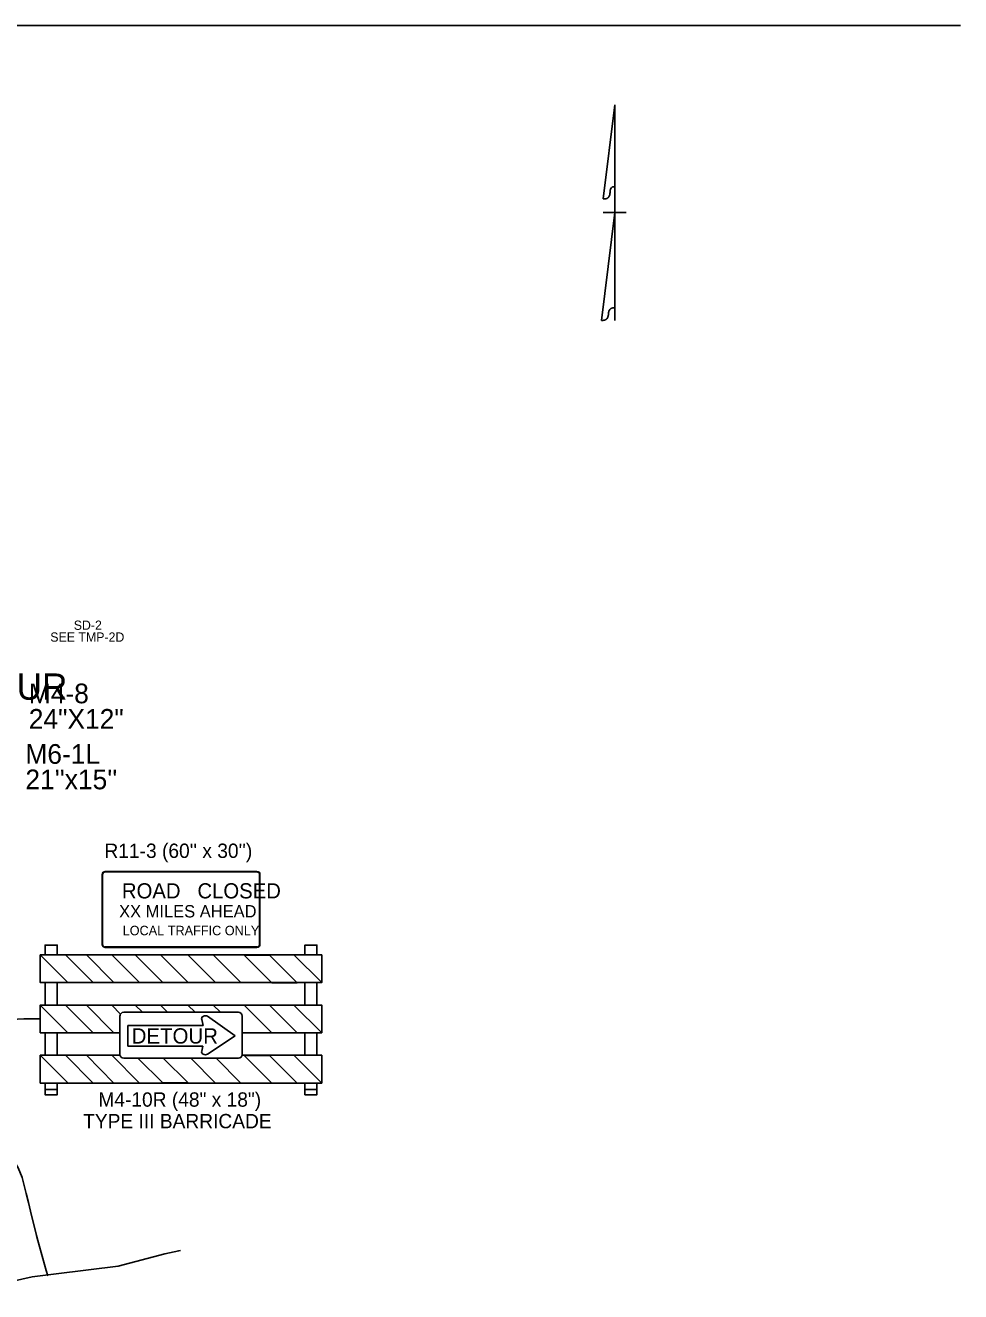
# Model space of a CAD drawing. Extents: x 886234 to 968767, y 455416 to 684046.
# Drawn here: x 928577 to 936553, y 478392 to 489183 of the extents above; entities that cross this region are included whole.
import ezdxf

# ---------------------------------------------------------------- set-up
doc = ezdxf.new("R2010")
doc.units = 0
for name, color, linetype in [('Scratch_Level_3', 7, 'Continuous'), ('TC DEV BARRICADE', 7, 'Continuous'), ('TC DEV SIGN BLACK 239', 7, 'Continuous'), ('TC DEV SIGN BLACK ZERO', 7, 'Continuous'), ('TC DEV SIGN ORANGE', 7, 'Continuous'), ('TC DEV SIGN WHITE', 7, 'Continuous'), ('TC LABEL TEXT', 7, 'Continuous'), ('TC SHEET LAYOUT SHAPE', 7, 'Continuous')]:
    doc.layers.add(name, color=color, linetype=linetype)

msp = doc.modelspace()

# ---------------------------------------------------------------- linework, layer by layer
at = {"layer": 'Scratch_Level_3'}
msp.add_line((904674, 489183), (936553, 489183), dxfattribs=at)
at = {"layer": 'TC DEV BARRICADE'}
for p, q in [((928921, 481261), (928705, 481261)), ((928705, 481261), (928940, 481026)), ((929157, 481026), (928921, 481261)), ((929314, 481261), (929098, 481261)), ((929098, 481261), (929333, 481026)), ((929550, 481026), (929314, 481261)), ((929730, 481261), (929514, 481261)), ((929514, 481261), (929749, 481026)), ((929965, 481026), (929730, 481261)), ((930180, 481261), (929964, 481261)), ((929964, 481261), (930200, 481026)), ((930416, 481026), (930180, 481261)), ((930660, 481260), (930444, 481260)), ((930444, 481260), (930679, 481025)), ((930895, 481025), (930660, 481260)), ((931105, 481261), (930867, 481261)), ((930867, 481261), (931105, 481026)), ((931105, 481026), (931105, 481261)), ((928940, 481026), (929157, 481026)), ((929333, 481026), (929550, 481026)), ((929749, 481026), (929965, 481026)), ((930200, 481026), (930416, 481026)), ((930679, 481025), (930895, 481025)), ((928921, 480834), (928705, 480834)), ((928705, 480834), (928940, 480598)), ((929157, 480598), (928921, 480834)), ((929314, 480833), (929098, 480833)), ((929098, 480833), (929333, 480598)), ((929314, 480833), (929098, 480833)), ((929098, 480833), (929333, 480598)), ((929390, 480758), (929314, 480833)), ((929390, 480758), (929314, 480833)), ((929730, 480834), (929514, 480834)), ((929514, 480834), (929575, 480773)), ((929514, 480834), (929575, 480773)), ((929791, 480773), (929730, 480834)), ((929791, 480773), (929730, 480834)), ((930180, 480833), (929964, 480833)), ((929964, 480833), (930025, 480773)), ((930180, 480833), (929964, 480833)), ((929964, 480833), (930025, 480773)), ((930241, 480773), (930180, 480833)), ((930241, 480773), (930180, 480833)), ((930660, 480832), (930444, 480832)), ((930444, 480832), (930679, 480597)), ((930895, 480597), (930660, 480832)), ((931105, 480834), (930867, 480834)), ((930867, 480834), (931105, 480598)), ((931105, 480598), (931105, 480834)), ((929384, 480598), (929384, 480740)), ((929575, 480773), (929791, 480773)), ((930025, 480773), (930241, 480773)), ((928940, 480598), (929157, 480598)), ((929333, 480598), (929384, 480598)), ((929333, 480598), (929384, 480598)), ((930679, 480597), (930895, 480597)), ((928921, 480406), (928705, 480406)), ((928705, 480406), (928940, 480171)), ((929157, 480170), (928921, 480406)), ((929314, 480406), (929098, 480406)), ((929098, 480406), (929333, 480170)), ((929550, 480170), (929314, 480406)), ((929538, 480382), (929749, 480171)), ((929538, 480382), (929749, 480171)), ((929754, 480382), (929538, 480382)), ((929965, 480171), (929754, 480382)), ((929965, 480171), (929754, 480382)), ((929988, 480382), (930200, 480170)), ((930204, 480382), (929988, 480382)), ((929988, 480382), (930199, 480170)), ((930416, 480170), (930204, 480382)), ((930415, 480170), (930204, 480382)), ((930660, 480404), (930444, 480404)), ((930444, 480404), (930679, 480169)), ((930895, 480169), (930660, 480404)), ((931105, 480406), (930867, 480406)), ((930867, 480406), (931105, 480170)), ((931105, 480170), (931105, 480406)), ((928940, 480171), (929157, 480170)), ((929333, 480170), (929550, 480170)), ((929749, 480171), (929965, 480171)), ((929749, 480171), (929965, 480171)), ((930200, 480170), (930416, 480170)), ((930679, 480169), (930895, 480169)), ((928746, 480116), (928849, 480116)), ((931064, 480116), (930962, 480116))]:
    msp.add_line(p, q, dxfattribs=at)
for points in [[(928746, 481263), (928746, 481346), (928849, 481346), (928849, 481263)], [(931064, 481263), (931064, 481346), (930962, 481346), (930962, 481263)], [(929317, 481261), (928705, 481261), (928705, 481026), (931105, 481026), (931105, 481261), (930542, 481261)], [(930542, 481261), (929317, 481261)], [(928746, 480836), (928746, 481027)], [(928849, 481028), (928849, 480838)], [(930962, 481028), (930962, 480838)], [(931064, 480836), (931064, 481027)], [(929317, 480834), (928705, 480834), (928705, 480598), (929384, 480598)], [(930542, 480834), (929317, 480834)], [(929730, 480834), (929730, 480834), (929514, 480834)], [(930426, 480598), (931105, 480598), (931105, 480834), (930542, 480834)], [(928746, 480406), (928746, 480598)], [(928849, 480597), (928849, 480408)], [(930962, 480597), (930962, 480408)], [(931064, 480406), (931064, 480598)], [(929317, 480406), (928705, 480406), (928705, 480170), (931105, 480170), (931105, 480406), (930542, 480406)], [(929384, 480406), (929317, 480406)], [(930542, 480406), (930426, 480406)], [(928849, 480169), (928849, 480070), (928746, 480070), (928746, 480170)], [(930199, 480170), (930200, 480170), (930415, 480170)], [(930962, 480169), (930962, 480070), (931064, 480070), (931064, 480170)]]:
    msp.add_lwpolyline(points, dxfattribs=at)
msp.add_arc((929417, 480740), 32.6, 146.236, 180, dxfattribs=at)
at = {"layer": 'TC DEV SIGN BLACK 239'}
msp.add_line((930552, 481326), (929259, 481326), dxfattribs=at)
for points in [[(929259, 481972), (930552, 481972)], [(929233, 481351), (929233, 481947)], [(930578, 481947), (930578, 481351)]]:
    msp.add_lwpolyline(points, dxfattribs=at)
for centre, start, end in [((929259, 481947), 90, 180), ((930552, 481947), 0, 90), ((929259, 481351), 180, 270.0009), ((930552, 481351), 270.0009, 360)]:
    msp.add_arc(centre, 25.9, start, end, dxfattribs=at)
at = {"layer": 'TC DEV SIGN BLACK ZERO'}
for p, q in [((929384, 480740), (929384, 480414)), ((930394, 480773), (929417, 480773)), ((930093, 480660), (930081, 480712)), ((930131, 480739), (930368, 480572)), ((930426, 480414), (930426, 480740)), ((929450, 480485), (929450, 480660)), ((929450, 480660), (930093, 480660)), ((930368, 480572), (930131, 480415)), ((930091, 480485), (929450, 480485)), ((930081, 480442), (930091, 480485)), ((929417, 480382), (930394, 480382))]:
    msp.add_line(p, q, dxfattribs=at)
for points in [[(929384, 480414), (929384, 480740)], [(929417, 480773), (930394, 480773)], [(930426, 480740), (930426, 480414)], [(930394, 480382), (929417, 480382)]]:
    msp.add_lwpolyline(points, dxfattribs=at)
for centre, start, end in [((929417, 480740), 90, 180), ((929417, 480740), 90, 180), ((930394, 480740), 360, 90), ((930394, 480740), 360, 90), ((929417, 480414), 180, 270), ((929417, 480414), 180, 270), ((930394, 480414), 270, 0), ((930394, 480414), 270, 360)]:
    msp.add_arc(centre, 32.6, start, end, dxfattribs=at)
for centre, start_param, end_param in [((930113, 480719), 0.96961, 3.452569), ((930113, 480435), 2.830617, 5.313577)]:
    msp.add_ellipse(centre, major_axis=(33, 0), ratio=0.720018, start_param=start_param, end_param=end_param, dxfattribs=at)
at = {"layer": 'TC DEV SIGN ORANGE'}
for p, q in [((930093, 480660), (930081, 480712)), ((930131, 480739), (930368, 480572)), ((929450, 480485), (929450, 480660)), ((929450, 480660), (930093, 480660)), ((930368, 480572), (930131, 480415)), ((930091, 480485), (929450, 480485)), ((930081, 480442), (930091, 480485))]:
    msp.add_line(p, q, dxfattribs=at)
for centre, start_param, end_param in [((930113, 480719), 0.96961, 3.452569), ((930113, 480435), 2.830617, 5.313577)]:
    msp.add_ellipse(centre, major_axis=(33, 0), ratio=0.720018, start_param=start_param, end_param=end_param, dxfattribs=at)
at = {"layer": 'TC DEV SIGN WHITE'}
msp.add_line((930552, 481329), (929259, 481329), dxfattribs=at)
for points in [[(929259, 481969), (930552, 481969)], [(929236, 481351), (929236, 481947)], [(930575, 481947), (930575, 481351)]]:
    msp.add_lwpolyline(points, dxfattribs=at)
for centre, start, end in [((929259, 481947), 90, 180), ((930552, 481947), 0, 90), ((929259, 481351), 180, 270.0009), ((930552, 481351), 270.0009, 360)]:
    msp.add_arc(centre, 22.6, start, end, dxfattribs=at)
at = {"layer": 'TC LABEL TEXT'}
for points in [[(928705, 480716), (928565, 480716), (927023, 480638)], [(927854, 480297), (927893, 480241), (928061, 480015), (928276, 479757), (928444, 479557), (928486, 479497), (928512, 479454), (928530, 479412), (928549, 479366), (928565, 479309), (928585, 479228), (928603, 479151)], [(928603, 479151), (928620, 479078), (928673, 478869)], [(928673, 478869), (928683, 478828), (928756, 478571), (928769, 478528)], [(929900, 478743), (929886, 478740), (929768, 478713), (929368, 478609), (928840, 478543), (928635, 478518), (928192, 478419), (927495, 478394), (927372, 478392), (926557, 478506), (926264, 478550), (925794, 478621), (925493, 478715), (925192, 478794)]]:
    msp.add_lwpolyline(points, dxfattribs=at)
at = {"layer": 'TC SHEET LAYOUT SHAPE'}
for p, q in [((933505, 487704), (933603, 488505)), ((933505, 487704), (933603, 488505)), ((933603, 486669), (933603, 488505)), ((933603, 488505), (933603, 487808)), ((933603, 488505), (933603, 487808)), ((933603, 487587), (933491, 486669)), ((933505, 487587), (933702, 487587)), ((933603, 486777), (933603, 487587))]:
    msp.add_line(p, q, dxfattribs=at)
for points in [[(933604, 487808), (933564, 487813), (933562, 487701), (933505, 487704)], [(933604, 487808), (933564, 487813), (933562, 487701), (933505, 487704)], [(933491, 486669), (933548, 486666), (933550, 486778), (933603, 486777)]]:
    msp.add_open_spline(points, degree=2, dxfattribs=at)

# ---------------------------------------------------------------- texts
at = {"layer": 'TC DEV BARRICADE'}
for s, p in [("R11-3 (60'' x 30'')", (929252, 482088)), ('M4-10R (48" x 18")', (929200, 479968)), ('TYPE III BARRICADE', (929070, 479784))]:
    msp.add_text(s, height=122.24, dxfattribs=at).set_placement(p)
at = {"layer": 'TC DEV SIGN BLACK 239'}
for s, height, p in [('ROAD   CLOSED', 129.36, (929401, 481743)), ('XX MILES AHEAD', 105.11, (929377, 481581)), ('LOCAL TRAFFIC ONLY', 80.85, (929407, 481429))]:
    msp.add_text(s, height=height, rotation=360, dxfattribs=at).set_placement(p)
at = {"layer": 'TC DEV SIGN BLACK ZERO'}
for height, p in [(224, (927671, 483436)), (130.3, (929484, 480506))]:
    msp.add_text('DETOUR', height=height, dxfattribs=at).set_placement(p)
for s, p in [('M4-8', (928607, 483406)), ('24"X12"', (928607, 483189)), ('M6-1L', (928578, 482890)), ("21''x15''", (928578, 482673))]:
    msp.add_text(s, height=168, rotation=360, dxfattribs=at).set_placement(p)
at = {"layer": 'TC LABEL TEXT'}
for s, p in [('SEE TMP-2D', (928790, 483931)), ('SD-2', (928990, 484032))]:
    msp.add_text(s, height=78.7, dxfattribs=at).set_placement(p)

doc.saveas('drawing.dxf')
